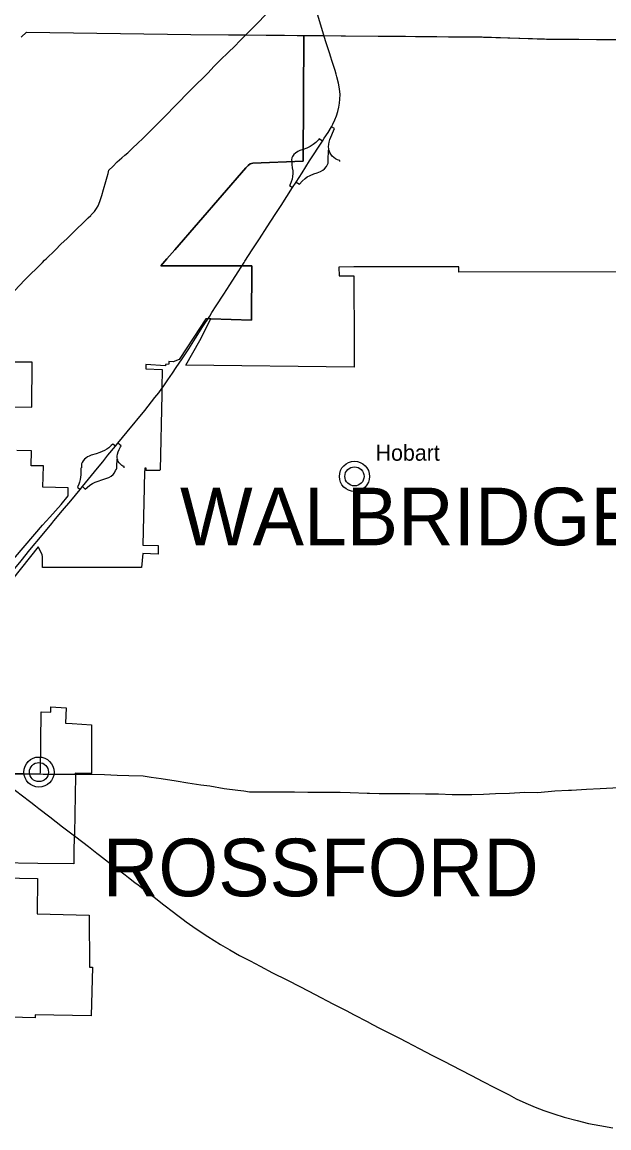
# Model space of a CAD drawing. Extents: x 0 to 851, y 0 to 440.
# Drawn here: x 352.8 to 378.43, y 311.68 to 359.94 of the extents above; entities that cross this region are included whole.
import ezdxf

# ---------------------------------------------------------------- set-up
doc = ezdxf.new("R2010")
doc.units = 0
for name, color, linetype in [('DV_X_Corp_Line', 7, 'Continuous'), ('GM_X_Corporation_Text', 7, 'Continuous'), ('GM_X_County', 7, 'Continuous'), ('GM_X_Interchange_Ramps', 7, 'Continuous'), ('GM_X_Interstate_Route', 7, 'Continuous'), ('GM_X_State_Route', 7, 'Continuous')]:
    doc.layers.add(name, color=color, linetype=linetype)

msp = doc.modelspace()

# ---------------------------------------------------------------- linework, layer by layer
at = {"layer": 'DV_X_Corp_Line'}
for points in [[(352.751, 359.28), (352.988, 359.491), (360.171, 359.395), (365.108, 359.354), (365.076, 353.873), (362.877, 353.784), (362.757, 353.754), (362.673, 353.677), (362.569, 353.583), (359.463, 350.003), (359.127, 349.602), (358.865, 349.304), (362.834, 349.306), (362.818, 346.933), (361.042, 346.985), (360.855, 346.988), (360.817, 346.989), (360.297, 346.194), (359.661, 345.215), (359.4, 345.107), (359.205, 345.119), (359.21, 345.002), (359.068, 344.999), (359.066, 344.943), (358.21, 344.999), (358.209, 344.803), (358.912, 344.774), (358.901, 343.963), (358.895, 343.688), (358.822, 340.392), (358.818, 340.37), (358.732, 340.366), (358.632, 340.367), (358.432, 340.369), (358.217, 340.368), (358.218, 340.473), (358.16, 340.474), (358.161, 340.355), (358.149, 340.354), (358.137, 339.611), (358.079, 337.11), (358.748, 337.093), (358.746, 336.861), (358.744, 336.724), (358.072, 336.742), (358.013, 336.131), (353.686, 336.129), (353.697, 336.442), (353.695, 336.595), (353.671, 336.696), (353.494, 337.03), (349.218, 331.672)], [(379.084, 349.033), (371.878, 349.031), (371.881, 349.262), (371.816, 349.262), (367.284, 349.251), (366.639, 349.249), (366.64, 348.87), (367.291, 348.864), (367.301, 345.897), (367.304, 344.878), (359.955, 344.964), (360.568, 346.037), (361.042, 346.985), (362.818, 346.933), (362.834, 349.306), (358.865, 349.304), (359.127, 349.602), (359.463, 350.003), (362.569, 353.583), (362.673, 353.677), (362.757, 353.754), (362.877, 353.784), (365.076, 353.873), (365.108, 359.354), (371.594, 359.3), (372.896, 359.289), (375.703, 359.197), (379.013, 359.176)], [(350.581, 343.163), (353.226, 343.128), (353.244, 345.091), (350.967, 345.102)], [(349.212, 332.74), (353.686, 337.986), (354.006, 338.338), (354.499, 338.879), (354.804, 339.264), (354.813, 339.608), (353.707, 339.638), (353.727, 340.57), (353.189, 340.577), (353.203, 341.228), (352.567, 341.24)], [(352.164, 327.164), (353.591, 327.124), (353.598, 327.185), (353.628, 329.836), (354.048, 329.822), (354.048, 330.049), (354.724, 330.012), (354.7, 329.336), (354.986, 329.326), (355.832, 329.273), (355.823, 327.148), (355.123, 327.162), (355.126, 327.042), (355.081, 324.508), (355.07, 324.352), (355.062, 323.782), (355.062, 323.197), (353.486, 323.221), (351.762, 323.252)], [(351.088, 322.61), (353.473, 322.569), (353.452, 321.024), (355.734, 320.963), (355.747, 318.691), (355.867, 318.697), (355.809, 316.575), (353.372, 316.62), (353.371, 316.477), (351.135, 316.534)]]:
    msp.add_lwpolyline(points, dxfattribs=at)
for centre, radius in [((367.315, 340.112), 0.658), ((367.315, 340.112), 0.417), ((353.535, 327.206), 0.658), ((353.535, 327.206), 0.417)]:
    msp.add_circle(centre, radius, dxfattribs=at)
at = {"layer": 'GM_X_County'}
msp.add_lwpolyline([(352.751, 359.28), (352.988, 359.491), (360.171, 359.395), (362.569, 359.375), (364.263, 359.361), (364.81, 359.356), (365.385, 359.352), (365.985, 359.347), (366.925, 359.339), (368.432, 359.326), (369.544, 359.317), (370.399, 359.309), (370.48, 359.309), (370.91, 359.305), (371.424, 359.3), (371.955, 359.295), (372.951, 359.287), (373.495, 359.269), (374.014, 359.252), (374.545, 359.235), (375.086, 359.217), (375.396, 359.207), (375.62, 359.204), (376.187, 359.197), (376.721, 359.19), (377.12, 359.188), (377.893, 359.183), (379.009, 359.176)], dxfattribs=at)
at = {"layer": 'GM_X_Interchange_Ramps'}
for points in [[(366.671, 353.852), (366.671, 353.903), (366.572, 353.933), (366.485, 353.973), (366.414, 354.023), (366.347, 354.09), (366.281, 354.179), (366.241, 354.247), (366.205, 354.333), (366.2, 354.358), (366.191, 354.405), (366.181, 354.494), (366.193, 354.607), (366.21, 354.701), (366.244, 354.809), (366.444, 355.293), (366.309, 355.366)], [(365.92, 354.746), (365.776, 354.836), (365.741, 354.795), (365.629, 354.684), (365.511, 354.593), (365.375, 354.503), (365.233, 354.437), (365.081, 354.376), (364.931, 354.329), (364.835, 354.29), (364.738, 354.222), (364.667, 354.153), (364.614, 354.075), (364.585, 354.012), (364.57, 353.928), (364.574, 353.85)], [(366.174, 353.861), (366.174, 353.908), (366.182, 354.355), (366.2, 354.358)], [(364.574, 353.85), (364.574, 353.832), (364.576, 353.717), (364.601, 353.571), (364.617, 353.453), (364.622, 353.336), (364.607, 353.2), (364.589, 353.079), (364.553, 352.966), (364.505, 352.855), (364.481, 352.804), (364.61, 352.716)], [(364.769, 352.956), (364.913, 352.866), (365.031, 352.995), (365.16, 353.109), (365.256, 353.183), (365.379, 353.247), (365.547, 353.32), (365.692, 353.366), (365.833, 353.417), (365.936, 353.474), (366.011, 353.54), (366.09, 353.637), (366.161, 353.774), (366.173, 353.821), (366.174, 353.861)], [(356.878, 341.426), (356.76, 341.518), (356.694, 341.454), (356.589, 341.362), (356.496, 341.299), (356.399, 341.245), (356.302, 341.196), (356.189, 341.155), (356.032, 341.103), (355.816, 341.036), (355.73, 340.999), (355.656, 340.96), (355.587, 340.912), (355.523, 340.863), (355.463, 340.79), (355.417, 340.714), (355.397, 340.658), (355.394, 340.575), (355.392, 340.492)], [(357.261, 340.481), (357.261, 340.543), (357.195, 340.562), (357.148, 340.593), (357.081, 340.657), (357.041, 340.705), (357.001, 340.767), (356.977, 340.819), (356.964, 340.866), (356.951, 340.922), (356.955, 340.99), (356.969, 341.078), (357, 341.19), (357.045, 341.287), (357.102, 341.401), (357.128, 341.439), (356.978, 341.556)], [(356.93, 340.48), (356.93, 340.557), (356.952, 340.863), (356.964, 340.866)], [(355.358, 340.492), (355.358, 340.466), (355.358, 340.183), (355.356, 340.077), (355.339, 339.976), (355.313, 339.866), (355.277, 339.77), (355.233, 339.674), (355.213, 339.64), (355.329, 339.543)], [(355.431, 339.665), (355.56, 339.556), (355.638, 339.629), (355.756, 339.722), (355.875, 339.802), (355.997, 339.865), (356.126, 339.907), (356.278, 339.96), (356.452, 340.015), (356.584, 340.064), (356.689, 340.124), (356.771, 340.191), (356.834, 340.27), (356.885, 340.368), (356.923, 340.433), (356.93, 340.463), (356.93, 340.48)]]:
    msp.add_lwpolyline(points, dxfattribs=at)
at = {"layer": 'GM_X_Interstate_Route'}
for points in [[(366.258, 358.507), (366.155, 358.809), (366.068, 359.07), (361.74, 373.464)], [(366.516, 357.664), (366.474, 357.821), (366.356, 358.177), (366.261, 358.498), (366.258, 358.506), (366.258, 358.507)], [(365.345, 353.876), (365.92, 354.746), (365.999, 354.873), (366.163, 355.117), (366.309, 355.366), (366.376, 355.488), (366.461, 355.677), (366.529, 355.85), (366.591, 356.033), (366.632, 356.22), (366.66, 356.393), (366.681, 356.567), (366.684, 356.779), (366.66, 357.028), (366.616, 357.277), (366.547, 357.548), (366.517, 357.659), (366.516, 357.664)], [(362.495, 349.448), (362.532, 349.507), (362.852, 349.992), (363.169, 350.484), (363.507, 351.006), (363.848, 351.548), (364.109, 351.94), (364.61, 352.716), (364.769, 352.956), (365.025, 353.364), (365.345, 353.876)], [(361.093, 347.264), (361.272, 347.549), (361.606, 348.06), (361.871, 348.476), (362.233, 349.038), (362.491, 349.442), (362.495, 349.448)], [(358.904, 343.942), (358.963, 344.022), (359.161, 344.319), (359.365, 344.61), (359.529, 344.857), (359.786, 345.247), (360.078, 345.682), (360.367, 346.148), (360.691, 346.65), (360.994, 347.106), (361.091, 347.261), (361.093, 347.264)], [(358.155, 342.99), (358.603, 343.552), (358.769, 343.755), (358.903, 343.94), (358.904, 343.942)], [(356.098, 340.477), (356.319, 340.75), (356.55, 341.033), (356.878, 341.426), (356.978, 341.556), (357.392, 342.062), (358.155, 342.99)], [(355.329, 339.543), (355.431, 339.665), (356.098, 340.477)], [(354.101, 338.062), (354.187, 338.165), (354.563, 338.619), (354.922, 339.046), (355.329, 339.543)], [(349.31, 332.298), (349.418, 332.43), (349.903, 333.03), (350.772, 334.013), (351.141, 334.46), (351.524, 334.923), (351.928, 335.41), (352.335, 335.92), (352.752, 336.42), (353.142, 336.9), (353.676, 337.545), (354.098, 338.057), (354.101, 338.062)], [(351.549, 327.147), (351.549, 327.147), (352.188, 326.655), (352.751, 326.221), (353.174, 325.898), (353.383, 325.737), (353.529, 325.618)], [(353.529, 325.618), (354.011, 325.253), (354.57, 324.819), (355.139, 324.375), (355.693, 323.956), (356.058, 323.673), (356.184, 323.578), (356.706, 323.171), (357.302, 322.72), (357.443, 322.604), (357.725, 322.387), (357.866, 322.282), (358.088, 322.113), (358.425, 321.854), (358.566, 321.742), (358.985, 321.42), (359.407, 321.097), (359.548, 320.992), (359.83, 320.775), (359.971, 320.669), (360.405, 320.364), (360.914, 320.026), (361.466, 319.676), (361.878, 319.45), (362.29, 319.207), (362.755, 318.963), (363.2, 318.73), (363.738, 318.451), (364.363, 318.145), (364.963, 317.834), (365.602, 317.498), (366.372, 317.089), (366.686, 316.927), (366.946, 316.795), (367.307, 316.616), (367.863, 316.321), (368.096, 316.196), (368.41, 316.033), (368.962, 315.752), (369.277, 315.59), (369.587, 315.428), (370.139, 315.146), (370.454, 314.984), (370.691, 314.859), (371.223, 314.584)], [(371.223, 314.584), (371.946, 314.21), (372.429, 313.963), (372.92, 313.706), (373.437, 313.441), (374.067, 313.117), (374.384, 312.95), (374.803, 312.755), (375.213, 312.587), (375.593, 312.439), (376.021, 312.291), (376.468, 312.145), (377.042, 311.996), (377.53, 311.876), (378.035, 311.783), (378.598, 311.679)]]:
    msp.add_lwpolyline(points, dxfattribs=at)
at = {"layer": 'GM_X_State_Route'}
for points in [[(360.651, 357.452), (360.917, 357.716), (361.188, 358.014), (361.465, 358.295), (361.797, 358.605), (362.085, 358.893), (362.315, 359.119), (371.724, 368.617)], [(358.226, 355.011), (358.411, 355.19), (358.628, 355.416), (358.825, 355.619), (359.141, 355.92), (359.407, 356.205), (359.651, 356.445), (359.996, 356.805), (360.16, 356.971), (360.267, 357.08), (360.49, 357.306), (360.631, 357.432), (360.651, 357.452)], [(357.279, 354.126), (357.41, 354.237), (357.62, 354.429), (357.85, 354.654), (358.07, 354.857), (358.226, 355.011)], [(356.591, 353.471), (356.764, 353.641), (356.946, 353.833), (357.151, 354.019), (357.279, 354.126)], [(355.817, 351.521), (355.879, 351.589), (355.963, 351.679), (356.055, 351.802), (356.126, 351.926), (356.194, 352.105), (356.277, 352.367), (356.358, 352.635), (356.458, 352.977), (356.514, 353.181), (356.557, 353.327), (356.574, 353.409), (356.591, 353.471)], [(353.781, 349.549), (353.843, 349.612), (354.239, 349.98), (354.504, 350.257), (354.749, 350.483), (354.973, 350.703), (355.211, 350.932), (355.432, 351.151), (355.685, 351.395), (355.8, 351.502), (355.817, 351.521)], [(350.588, 346.375), (350.675, 346.465), (350.849, 346.628), (351.149, 346.924), (351.565, 347.317), (351.764, 347.529), (352.075, 347.839), (352.482, 348.231), (352.911, 348.67), (353.689, 349.453), (353.781, 349.549)], [(352.366, 327.135), (353.06, 327.132), (353.591, 327.124)], [(353.591, 327.124), (353.725, 327.122), (354.676, 327.111), (355.147, 327.11)], [(355.147, 327.11), (355.545, 327.109), (355.839, 327.109)], [(355.839, 327.109), (356.403, 327.107), (356.956, 327.075), (357.458, 327.062), (358.085, 327.039), (358.44, 326.988), (358.873, 326.924), (359.527, 326.824), (360.032, 326.739), (360.606, 326.652), (361.003, 326.601), (361.629, 326.496), (362.221, 326.415), (362.484, 326.382), (362.727, 326.349), (362.945, 326.35), (363.419, 326.338), (363.728, 326.338), (364.053, 326.338), (364.695, 326.342), (365.279, 326.337), (365.76, 326.325), (366.218, 326.332), (366.698, 326.328), (367.123, 326.319), (367.867, 326.281), (367.978, 326.28), (368.388, 326.278), (368.922, 326.274)], [(368.922, 326.274), (368.982, 326.274), (369.096, 326.273), (369.727, 326.267), (370.425, 326.263), (370.983, 326.252), (371.587, 326.233), (371.769, 326.231)], [(371.769, 326.231), (371.855, 326.231)], [(371.855, 326.231), (371.875, 326.23), (372.038, 326.229), (372.442, 326.235), (372.95, 326.242), (373.475, 326.269), (374.084, 326.291), (374.756, 326.324), (375.327, 326.319), (376.06, 326.385), (376.663, 326.416)], [(376.663, 326.416), (376.669, 326.417), (376.79, 326.423), (377.452, 326.463), (378.051, 326.488), (378.603, 326.521), (378.981, 326.542)]]:
    msp.add_lwpolyline(points, dxfattribs=at)

# ---------------------------------------------------------------- texts
at = {"layer": 'DV_X_Corp_Line'}
msp.add_text('Hobart', height=0.6979, rotation=0, dxfattribs=at).set_placement((368.241, 340.795))
at = {"layer": 'GM_X_Corporation_Text'}
for s, p in [('WALBRIDGE', (359.697, 337.105)), ('ROSSFORD', (356.324, 321.788))]:
    msp.add_text(s, height=2.5126, rotation=0, dxfattribs=at).set_placement(p)

doc.saveas('drawing.dxf')
